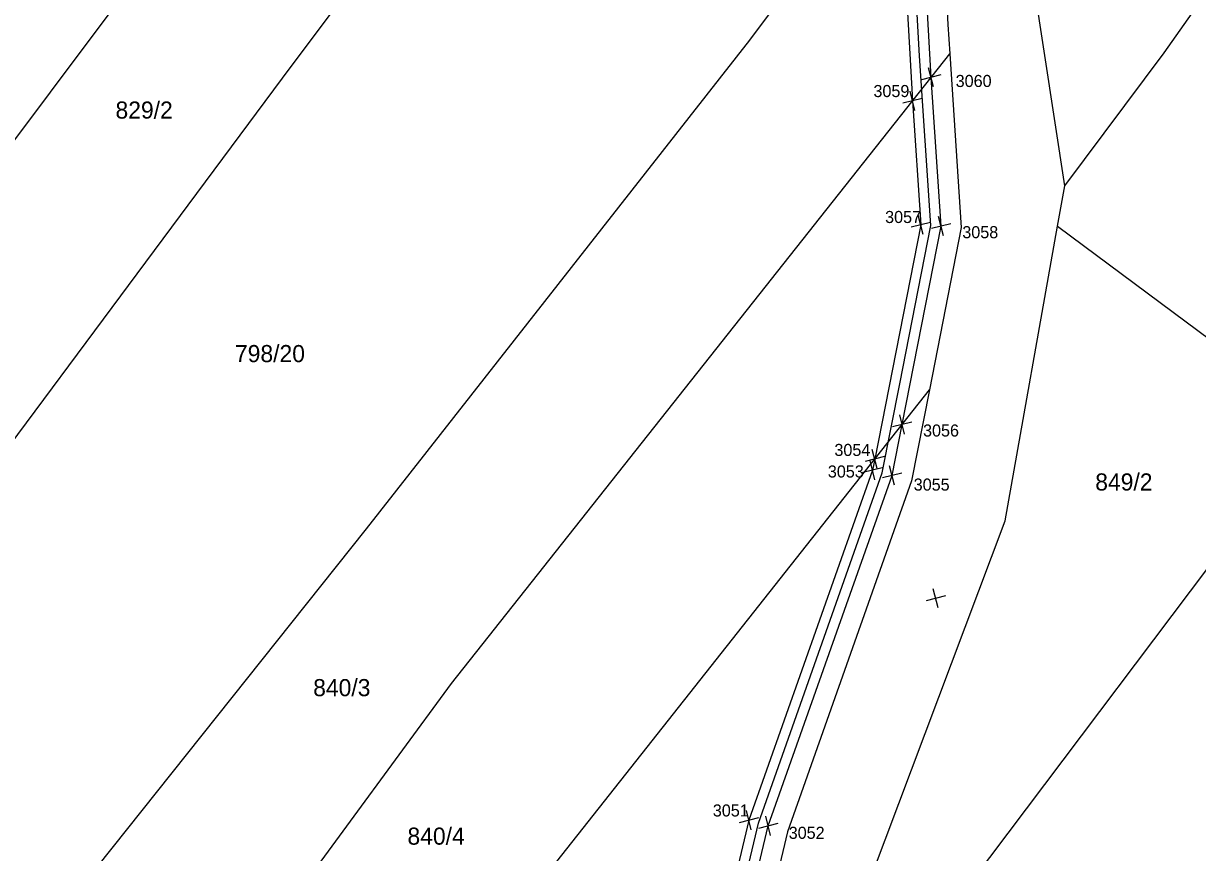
# Model space of a CAD drawing. Extents: x -7476540 to -746055, y -11317203 to -1129777.
# Drawn here: x -747663.2 to -747546.5, y -1131612.5 to -1131530.2 of the extents above; entities that cross this region are included whole.
import ezdxf

# ---------------------------------------------------------------- set-up
doc = ezdxf.new("R2010")
doc.units = 0
for name, color, linetype in [('_TRASA_vedení kabelu_CEZ', 7, 'Continuous'), ('Hranice parcel', 7, 'Continuous'), ('obvod_stavby_DZ_DO_ZPF', 7, 'Continuous'), ('Parcelní čísla', 7, 'Continuous'), ('Vrstva 60', 7, 'Continuous')]:
    doc.layers.add(name, color=color, linetype=linetype)

# ---------------------------------------------------------------- blocks, each defined once
blk = doc.blocks.new('POINT_DISPLAY')
for p, q in [((-0.7, -0.7), (0.7, 0.7)), ((-0.7, 0.7), (0.7, -0.7))]:
    blk.add_line(p, q)

msp = doc.modelspace()

# ---------------------------------------------------------------- linework, layer by layer
at = {"layer": '_TRASA_vedení kabelu_CEZ'}
msp.add_lwpolyline([(-747606.66, -1131708.94), (-747603.52, -1131695.37), (-747628.04, -1131689.7), (-747599.97, -1131653.35), (-747599.82, -1131650.35), (-747590.15, -1131609.62), (-747577.85, -1131574.83), (-747576.11, -1131566), (-747573.02, -1131550.26), (-747574.14, -1131533.4), (-747574.33, -1131530.46), (-747575.58, -1131507.34), (-747576.38, -1131492.52), (-747578.4, -1131453.5), (-747579.22, -1131437.56), (-747579.88, -1131425.59), (-747579.54, -1131395.96)], dxfattribs=at)
at = {"layer": 'Hranice parcel'}
for q in [(-747559.72, -1131546.32), (-747534.47, -1131569.66)]:
    msp.add_line((-747560.43, -1131550.33), q, dxfattribs=at)
for points in [[(-747751.97, -1131658.69), (-747725.51, -1131622.95), (-747709.1, -1131600.51), (-747691.54, -1131577.63), (-747669.23, -1131548.64), (-747625.65, -1131490.48), (-747576.88, -1131425.52)], [(-747575.4, -1131453.35), (-747596.53, -1131480.99), (-747637.49, -1131535.62), (-747681.61, -1131594.97), (-747707.2, -1131626.86), (-747733.77, -1131662.83)], [(-747559.72, -1131546.32), (-747549.84, -1131533.09), (-747519.12, -1131489.53), (-747492.83, -1131454.72)], [(-747559.72, -1131546.32), (-747562.72, -1131526.64), (-747564.97, -1131493.37)], [(-747698.69, -1131671.28), (-747664.74, -1131625.11), (-747629.09, -1131580.38), (-747591, -1131531.84), (-747572.58, -1131507.18)], [(-747572.58, -1131507.18), (-747571.34, -1131530.28), (-747571.15, -1131533.2)], [(-747680.04, -1131675.66), (-747646.64, -1131631.19), (-747620.64, -1131595.74), (-747571.15, -1131533.2)], [(-747571.15, -1131533.2), (-747570, -1131550.45), (-747573.17, -1131566.58)], [(-747582.84, -1131630.56), (-747581.53, -1131621.85), (-747565.63, -1131579.59), (-747560.43, -1131550.33)], [(-747660.92, -1131680.14), (-747626.14, -1131633.64), (-747573.17, -1131566.58)], [(-747573.17, -1131566.58), (-747574.95, -1131575.62), (-747587.27, -1131610.47), (-747596.84, -1131650.77)], [(-747582.84, -1131630.56), (-747574.44, -1131622.7), (-747534.47, -1131569.66)]]:
    msp.add_lwpolyline(points, dxfattribs=at)
at = {"layer": 'obvod_stavby_DZ_DO_ZPF'}
for points in [[(-747626.3, -1131689.08), (-747598.98, -1131653.55), (-747598.83, -1131650.49), (-747589.19, -1131609.9), (-747576.88, -1131575.09), (-747575.89, -1131570.02), (-747572.01, -1131550.32), (-747573, -1131535.54), (-747574.45, -1131509.68), (-747577.28, -1131455.8), (-747578.74, -1131428), (-747578.88, -1131425.6), (-747578.57, -1131398.49)], [(-747580.6, -1131401.09), (-747580.88, -1131425.73), (-747580.61, -1131430.49), (-747579.15, -1131458.31), (-747576.32, -1131512.18), (-747574.85, -1131537.87), (-747574.03, -1131550.19), (-747578.6, -1131573.46), (-747578.82, -1131574.56), (-747591.11, -1131609.34), (-747600.82, -1131650.21), (-747600.95, -1131652.99), (-747628.4, -1131688.54)]]:
    msp.add_lwpolyline(points, dxfattribs=at)
at = {"layer": 'Vrstva 60'}
for p, q in [((-747573, -1131535.54), (-747573, -1131535.54)), ((-747574.85, -1131537.87), (-747574.85, -1131537.87)), ((-747574.03, -1131550.19), (-747574.03, -1131550.19)), ((-747572.01, -1131550.32), (-747572.01, -1131550.32)), ((-747575.89, -1131570.02), (-747575.89, -1131570.02)), ((-747578.6, -1131573.46), (-747578.6, -1131573.46)), ((-747578.82, -1131574.56), (-747578.82, -1131574.56)), ((-747576.88, -1131575.09), (-747576.88, -1131575.09)), ((-747591.11, -1131609.34), (-747591.11, -1131609.34)), ((-747589.19, -1131609.9), (-747589.19, -1131609.9))]:
    msp.add_line(p, q, dxfattribs=at)

# ---------------------------------------------------------------- block references
at = {"layer": 'obvod_stavby_DZ_DO_ZPF', "rotation": 149.23018890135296}
for p in [(-747573, -1131535.54), (-747574.85, -1131537.87), (-747574.03, -1131550.19), (-747572.01, -1131550.32), (-747575.88, -1131570.02), (-747578.6, -1131573.45), (-747578.82, -1131574.56), (-747576.88, -1131575.09), (-747572.54, -1131587.29), (-747591.11, -1131609.34), (-747589.19, -1131609.9)]:
    msp.add_blockref('POINT_DISPLAY', p, dxfattribs=at)

# ---------------------------------------------------------------- texts
at = {"layer": 'Parcelní čísla'}
for s, p in [('829/2', (-747654.04, -1131539.64)), ('798/20', (-747642.17, -1131563.83)), ('849/2', (-747556.69, -1131576.58)), ('840/3', (-747634.4, -1131597.01)), ('840/4', (-747625.03, -1131611.76))]:
    msp.add_text(s, height=1.7, dxfattribs=at).set_placement(p)
at = {"layer": 'Vrstva 60'}
for s, p in [('3060', (-747570.56, -1131536.5)), ('3059', (-747578.73, -1131537.5)), ('3057', (-747577.57, -1131550.01)), ('3058', (-747569.9, -1131551.52)), ('3056', (-747573.8, -1131571.22)), ('3054', (-747582.61, -1131573.15)), ('3053', (-747583.26, -1131575.29)), ('3055', (-747574.73, -1131576.59)), ('3051', (-747594.69, -1131608.96)), ('3052', (-747587.15, -1131611.18))]:
    msp.add_text(s, height=1.2, dxfattribs=at).set_placement(p)

doc.saveas('drawing.dxf')
